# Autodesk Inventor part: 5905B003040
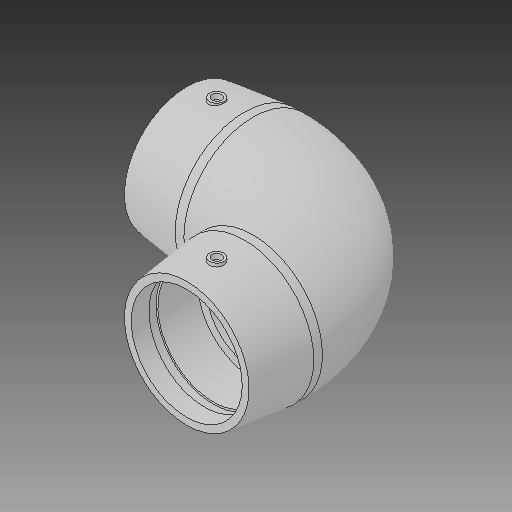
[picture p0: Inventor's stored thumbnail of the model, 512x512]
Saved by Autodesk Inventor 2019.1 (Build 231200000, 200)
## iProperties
Created: 2017-06
Part Number: 5905B003040
Material: Generic
Description: PLASSON 90° ELBOW ASTM 4''
Document SubType Name: Modeling
Designer: KIM
Mass: 55.0731 g
Surface Area: 148.067 cm^2
Volume: 55.0731 cm^3
Density: 1 g/cm^3
Appearance: Default
Author: KIM
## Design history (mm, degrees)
derived "5905B.ipt"
feature "Solid1::5905B.ipt"
tag "TaggingFeature1"
body "Solid1"
other parameters: "d_" = 114.1, "L_" = 237.49, "L_1" = 68.326, "D_" = 142.494, "A_" = 70.104, "d2" = 142.494, "d4" = 59.3725, "d5" = 128.2446, "d8" = 168 deg, "d10" = 27.3304, "d11" = 9.11013, "d14" = 17.6296, "d18" = 114.1, "d19" = 3.52592, "d20" = 168 deg, "d22" = 131.09448, "d23" = 142.494, "d24" = 127.16165, "d29" = 70.104, "d30" = 15, "d31" = 142.494, "d34" = 5 deg, "d35" = 15, "d39" = 5 deg, "d41" = 4, "d42" = 14, "d43" = 0, "d45" = 4, "d46" = 14, "d47" = 0, "d49" = 114.1, "d50" = 96.985, "d51" = 27.3304, "d52" = 68.326, "d54" = 90 deg, "d65" = 114.1, "d67" = 45 deg, "d71" = 90 deg, "d75" = 7.1247, "d82" = 45 deg, "d83" = 68.326, "d84" = 128.2446, "d86" = 64.1223, "d87" = 90 deg, "d90" = 68.326, "d91" = 0, "d92" = 68.326, "d93" = 0, "d94" = 90 deg, "d95" = 65.54724, "d98" = 237.49, "d101" = 3, "d102" = 0, "d103" = 3, "d104" = 0, "d105" = 19.81454, "d106" = 4.95363, "d107" = 237.49, "d110" = 37.5793
